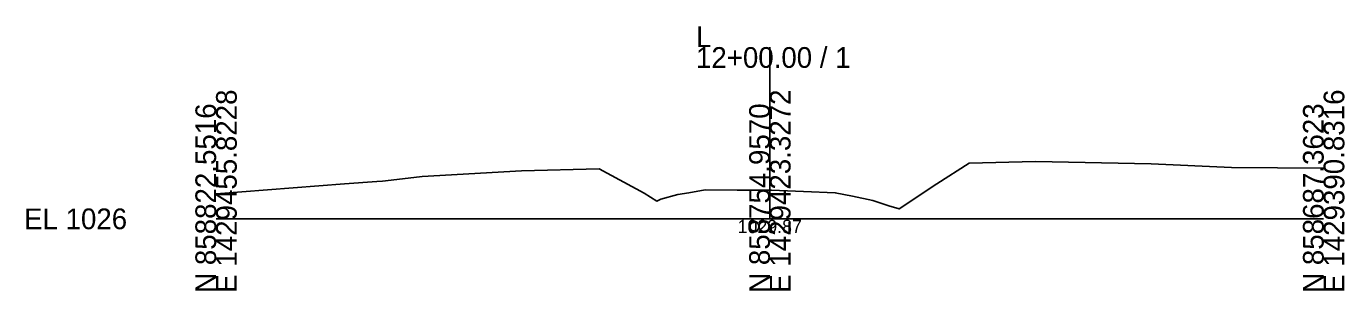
# Model space of a CAD drawing. Extents: x -26 to 176, y -10 to 13058.
# Drawn here: x -25.7 to 152.8, y 990.3 to 1026 of the extents above; entities that cross this region are included whole.
import ezdxf

# ---------------------------------------------------------------- set-up
doc = ezdxf.new("R2010")
doc.units = 0
for name, color, linetype in [('Default', 7, 'Continuous'), ('Exist Cross Section Cell', 7, 'Continuous'), ('Exist XS Center Line Elevation Label', 7, 'Continuous'), ('Exist XS Ground Line', 7, 'Continuous')]:
    doc.layers.add(name, color=color, linetype=linetype)

msp = doc.modelspace()

# ---------------------------------------------------------------- linework, layer by layer
at = {"layer": 'Exist Cross Section Cell'}
for p, q in [((75, 1000), (75, 1023.21)), ((0, 1000), (75, 1000)), ((75, 1000), (150, 1000))]:
    msp.add_line(p, q, dxfattribs=at)
at = {"layer": 'Exist XS Ground Line'}
msp.add_lwpolyline([(0, 1003.37), (17.39, 1004.75), (21.77, 1005.07), (22.56, 1005.11), (26.01, 1005.52), (27.93, 1005.71), (41.37, 1006.49), (51.9, 1006.75), (57.96, 1003.49), (59.67, 1002.38), (60.25, 1002.66), (62.55, 1003.31), (64.02, 1003.54), (66.23, 1003.91), (70.57, 1003.9), (75.2, 1003.87), (79.55, 1003.7), (83.86, 1003.53), (86.19, 1003.05), (88.93, 1002.48), (91.11, 1001.78), (92.5, 1001.35), (97.63, 1004.72), (101.97, 1007.54), (110.99, 1007.74), (126.65, 1007.45), (137.53, 1006.96), (150, 1006.83)], dxfattribs=at)
msp.add_lwpolyline([(0, 1003.37), (17.39, 1004.75), (21.77, 1005.07), (22.56, 1005.11), (26.01, 1005.52), (27.93, 1005.71), (41.37, 1006.49), (51.9, 1006.75), (57.96, 1003.49), (59.67, 1002.38), (60.25, 1002.66), (62.55, 1003.31), (64.02, 1003.54), (66.23, 1003.91), (70.57, 1003.9), (75.2, 1003.87), (79.55, 1003.7), (83.86, 1003.53), (86.19, 1003.05), (88.93, 1002.48), (91.11, 1001.78), (92.5, 1001.35), (97.63, 1004.72), (101.97, 1007.54), (110.99, 1007.74), (126.65, 1007.45), (137.53, 1006.96), (150, 1006.83)], dxfattribs=at)
msp.add_lwpolyline([(0, 1003.37), (17.39, 1004.75), (21.77, 1005.07), (22.56, 1005.11), (26.01, 1005.52), (27.93, 1005.71), (41.37, 1006.49), (51.9, 1006.75), (57.96, 1003.49), (59.67, 1002.38), (60.25, 1002.66), (62.55, 1003.31), (64.02, 1003.54), (66.23, 1003.91), (70.57, 1003.9), (75.2, 1003.87), (79.55, 1003.7), (83.86, 1003.53), (86.19, 1003.05), (88.93, 1002.48), (91.11, 1001.78), (92.5, 1001.35), (97.63, 1004.72), (101.97, 1007.54), (110.99, 1007.74), (126.65, 1007.45), (137.53, 1006.96), (150, 1006.83)], dxfattribs=at)

# ---------------------------------------------------------------- texts
at = {"layer": 'Default'}
msp.add_text('-', height=0.0001, dxfattribs=at).set_placement((0, 1000))
at = {"layer": 'Exist Cross Section Cell'}
for s, p in [('L', (65, 1023.21)), ('12+00.00 / 1', (65, 1020.41)), ('EL 1026', (-26, 998.6))]:
    msp.add_text(s, height=2.8, dxfattribs=at).set_placement(p)
for s, p in [('E 1429455.8228', (2.8, 990)), ('E 1429423.3272', (77.8, 990)), ('E 1429390.8316', (152.8, 990)), ('N 858822.5516', (0, 990)), ('N 858754.9570', (75, 990)), ('N 858687.3623', (150, 990))]:
    msp.add_text(s, height=2.8, rotation=90, dxfattribs=at).set_placement(p)
at = {"layer": 'Exist XS Center Line Elevation Label'}
msp.add_text('1029.87', height=1.8, dxfattribs=at).set_placement((70.63, 998.07))
msp.add_text('1029.87', height=1.8, dxfattribs=at).set_placement((70.63, 998.07))
msp.add_text('1029.87', height=1.8, dxfattribs=at).set_placement((70.63, 998.07))

doc.saveas('drawing.dxf')
